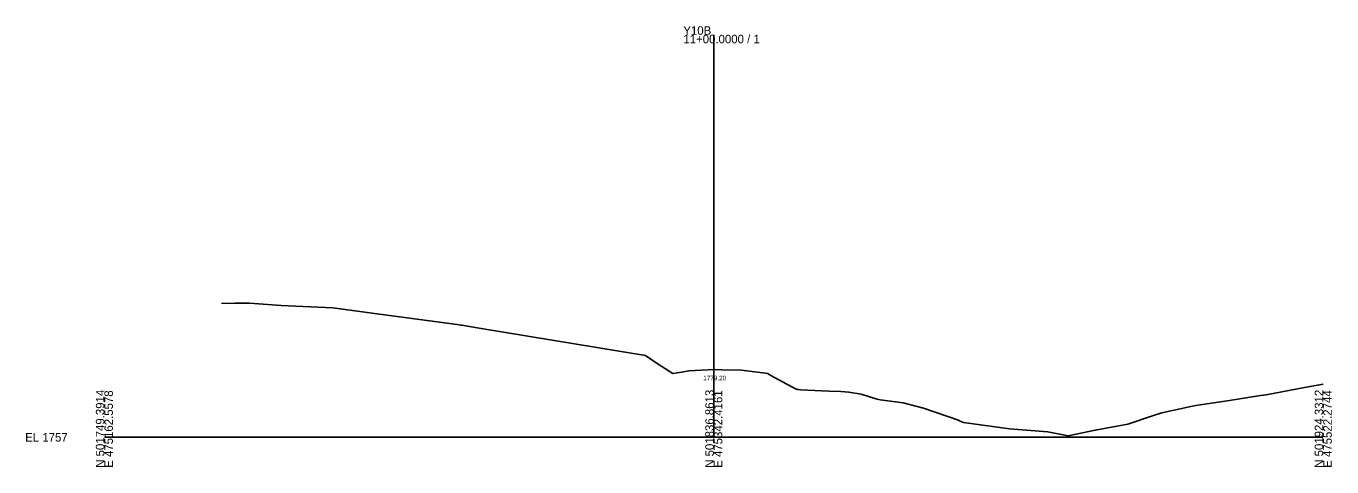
# Model space of a CAD drawing. Extents: x -26 to 1803, y -10 to 9558.
# Drawn here: x -25.7 to 402.8, y 990.3 to 1134.9 of the extents above; entities that cross this region are included whole.
import ezdxf

# ---------------------------------------------------------------- set-up
doc = ezdxf.new("R2010")
doc.units = 0
for name, color, linetype in [('Exist Cross Section Cell', 7, 'Continuous'), ('Exist XS Center Line Elevation Label', 7, 'Continuous'), ('Exist XS Ground Line', 7, 'Continuous')]:
    doc.layers.add(name, color=color, linetype=linetype)

msp = doc.modelspace()

# ---------------------------------------------------------------- linework, layer by layer
at = {"layer": 'Exist Cross Section Cell'}
for p, q in [((200, 1000), (200, 1132.03)), ((0, 1000), (200, 1000)), ((200, 1000), (400, 1000))]:
    msp.add_line(p, q, dxfattribs=at)
at = {"layer": 'Exist XS Ground Line'}
msp.add_lwpolyline([(38.4, 1043.84), (42.77, 1044.01), (47.59, 1043.97), (57.97, 1043.24), (74.96, 1042.48), (91.96, 1040.2), (115.76, 1036.98), (116.94, 1036.84), (117.35, 1036.77), (123.02, 1035.84), (177.56, 1026.85), (181.72, 1024.03), (186.53, 1020.89), (189.42, 1021.36), (191.89, 1021.85), (195.9, 1022.01), (200.29, 1022.21), (202.66, 1022.18), (209.12, 1022.04), (216.97, 1021), (217.75, 1020.9), (218.52, 1020.4), (227.07, 1015.82), (227.47, 1015.69), (227.79, 1015.64), (228.58, 1015.62), (237.79, 1015.14), (241.68, 1015.01), (244.26, 1014.82), (248.33, 1014.12), (251.08, 1013.25), (253.61, 1012.54), (254.54, 1012.34), (262.18, 1011.26), (268.84, 1009.55), (280.35, 1005.63), (280.88, 1005.35), (281.9, 1004.88), (297.06, 1002.79), (309.59, 1001.76), (316.27, 1000.53), (325.15, 1002.34), (335.91, 1004.36), (343.97, 1007.04), (347.04, 1007.98), (356.59, 1010.14), (358.16, 1010.39), (359.65, 1010.64), (369.28, 1012.07), (379.45, 1013.68), (380.4, 1013.81), (381.3, 1013.98), (391.52, 1015.87), (395.06, 1016.57), (400, 1017.44)], dxfattribs=at)

# ---------------------------------------------------------------- texts
at = {"layer": 'Exist Cross Section Cell'}
for s, p in [('Y10B', (190, 1132.03)), ('11+00.0000 / 1', (190, 1129.23)), ('EL 1757', (-26, 998.6))]:
    msp.add_text(s, height=2.8, dxfattribs=at).set_placement(p)
for s, p in [('N 501749.3914', (0, 990)), ('E 475162.5578', (2.8, 990)), ('N 501836.8613', (200, 990)), ('E 475342.4161', (202.8, 990)), ('N 501924.3312', (400, 990)), ('E 475522.2744', (402.8, 990))]:
    msp.add_text(s, height=2.8, rotation=90, dxfattribs=at).set_placement(p)
at = {"layer": 'Exist XS Center Line Elevation Label'}
msp.add_text('1779.20', height=1.5, dxfattribs=at).set_placement((196.56, 1018.7))

doc.saveas('drawing.dxf')
